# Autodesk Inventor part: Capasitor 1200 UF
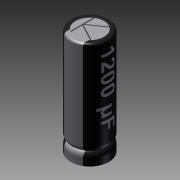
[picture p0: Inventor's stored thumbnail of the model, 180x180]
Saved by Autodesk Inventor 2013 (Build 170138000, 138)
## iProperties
Company: Autodesk Inc.
Created: 2005-12
Part Number: Capasitor 1200 UF
Document SubType Name: Modeling
Designer: Autodesk Inc.
Density: 1 g/cm^3
Mass: 1.11841 g
Surface Area: 6.73474 cm^2
Volume: 1.11841 cm^3
Material: Allgemein
Title: Personal Computer
Author: Autodesk Inc.
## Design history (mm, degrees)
sketch "Sketch1"
  geometry: L1 (0, 5.6)-(0, -5.6) reference; L2 (-5.6, 0)-(5.6, 0) reference; C1 r 4 at (0, 0)
  constraints: 2 midpoint, 1 centre point
  dimensions: "d0" = 8 diameter of C1
extrude "Extrusion1" new body sketch "Sketch1" distance "d1" = 22.5; taper "d2" = 0 deg
revolve "Revolution1" stored, may be unused: angle "d19" = 90 deg
sketch "Sketch2"
  geometry: C1 r 4 at (0, 0) reference; C2 r 3 at (0, 0)
  constraints: 1 centre point, 1 coincident
  dimensions: "d3" = 1 radial gap between concentric circles of C2 C1
extrude "Extrusion2" cut sketch "Sketch2" distance "d4" = 0.1; taper "d5" = 0 deg
sketch "Sketch3"
  geometry: L1 (-1.735, 2.896)-(-1.471, 2.896); L2 (-1.471, 2.896)-(-1.471, -3.053); L3 (-1.471, -3.053)-(-1.735, -3.053); L4 (-1.735, -3.053)-(-1.735, 2.896); L5 (-1.471, 0.123)-(-1.596, 0.302); L6 (-1.596, 0.302)-(1.797, 2.672); L7 (1.797, 2.672)-(1.922, 2.493); L8 (1.922, 2.493)-(-1.471, 0.123); L9 (-1.471, 0.123)-(-1.578, -0.079); L10 (-1.578, -0.079)-(2.364, -2.162); L11 (2.364, -2.162)-(2.47, -1.96); L12 (2.47, -1.96)-(-1.471, 0.123)
  constraints: 24 end point, 6 parallel, 3 perpendicular, 1 horizontal, 1 point on line
extrude "Extrusion3" cut sketch "Sketch3" distance "d6" = 0.05; taper "d7" = 0 deg
fillet "Fillet1" dims "d8" = 0.5
sketch "Sketch5"
  geometry: L1 (2, -2.236)-(2, -5); L2 (2, -5)-(-2, -5); L3 (-2, -5)-(-2, -2.236); L4 (0, -6.8)-(0, 5.8) reference; A1 r 3 centre (0, 0) between (-2, -2.236) and (2, -2.236) reference; 3 further points
  constraints: 6 end point, 2 point on circle, 1 coincident, 1 parallel, 1 point on line, 1 vertical alignment, 2 other
  dimensions: "d12" = 1 distance from line of L2 point (0, -4); "d13" = 4 distance of L1.end L2.end
split "Split1" sketch "Sketch5"
workplane "Work Plane1"
sketch "Sketch4"
  geometry: L1 (-21.256, 1.635)-(-5.648, 1.635); L2 (-5.648, 1.635)-(-5.648, -2.204); L3 (-5.648, -2.204)-(-21.256, -2.204); L4 (-21.256, -2.204)-(-21.256, 1.635)
  constraints: 2 other
emboss "Emboss1" sketch "Sketch4" dims "d8" = 0.5, "d10" = 0.05, "d11" = 0
body "Solid1"
sketch "Sketch6"
  geometry: L1 (0, 27)-(0, -4.5) reference; L2 (4, 0)-(4, 22.5) reference; L3 (4, 3.5)-(4, 1.5); L4 (4, 2.5)-(3.5, 2.5); L5 (-4, 0)-(4, 0) reference; A1 r 1.25 centre (2.75, 3.5) between (3.5, 2.5) and (4, 3.5); A2 r 1.25 centre (2.75, 1.5) between (4, 1.5) and (3.5, 2.5); 1 further point
  constraints: 4 end point, 4 point on circle, 2 centre point, 2 point on line, 2 tangent, 1 collinear, 1 horizontal, 1 midpoint
  dimensions: "d16" = 2 distance of L3.start L3.end; "d17" = 2.5 distance between parallel lines of L5 L4; "d18" = 0.5 distance of L4.start L4.end
